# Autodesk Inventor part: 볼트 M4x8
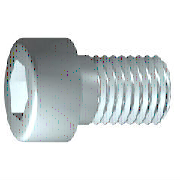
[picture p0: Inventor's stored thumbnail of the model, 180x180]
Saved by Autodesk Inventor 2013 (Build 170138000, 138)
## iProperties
Created: 2012-02
Part Number: 볼트 M4x8
Material: 스테인리스강
Description: 6각 소켓 머리 캡 나사
Document SubType Name: Modeling
Standard: ISO 4762
Designer: mduedu
Standard Revision: Fourth edition 2004-03-01
Standards Organization: ISO
Language: ko-KR
Size Designation: M4 x 8
Categories: <MemberInstance><Categories><Category DisplayName="조임쇠" InternalName="e4da775c-781d-43d5-af7c-5136215cf5a6" Mnemonic="FSTN"><Category DisplayName="볼트" InternalN
Density: 8.08 g/cm^3
Mass: 1.89105 g
Surface Area: 2.80587 cm^2
Volume: 0.234041 cm^3
IsCustomPart: 0
Author: mduedu
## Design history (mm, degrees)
sketch "스케치1"
  geometry: L1 (-1, 0)-(8, 0); L2 (8, 0)-(8, 2); L3 (8, 2)-(1.75, 2); L4 (1.75, 2)-(1.32, 2); L5 (1.32, 2)-(0, 2); L6 (0, 2)-(0, 3.5); L7 (0, 3.5)-(-4, 3.5); L8 (-4, 3.5)-(-4, 1.732); L9 (-4, 1.732)-(-2, 1.732); L10 (-2, 1.732)-(-1, 0); L11 (-6.4, 0)-(10.4, 0) reference; L12 (0, -0.7)-(0, 4.2) reference; L13 (1.75, 2)-(0, 2)
  constraints: 22 end point, 6 parallel, 2 collinear, 2 perpendicular, 1 horizontal, 1 point on line
  dimensions: "d1" = 6.25 distance from line of L3.end L2 (= GEL); "d2" = 0.42952 distance of L4.end L3.end (computed from GAL); "d3" = 4 distance between parallel lines of L8 L6 (= KOH); "d4" = 2 distance of L8.end L9.end (= INTI); "d5" = 60 deg angle of L10 L1; "d6" = 4 diameter of L3 L1 (= GD); "d7" = 4 diameter of L5 L1 (= BDM); "d8" = 3.4641 diameter of L9 L1 (= 1.1547 x SW); "d9" = 7 diameter of L7 L1 (= KOD); "d26" = 8 distance between parallel lines of L12 L2 (= NLG)
revolve "본체" sketch "스케치1" stored, may be unused: angle "d10" = 90 deg
sketch "스케치2"
  geometry: L1 (0, -4.9)-(0, 4.9) reference; L2 (-4.9, 0)-(4.9, 0) reference; L3 (1.732, 0)-(0.866, -1.5); L4 (0.866, -1.5)-(-0.866, -1.5); L5 (-0.866, -1.5)-(-1.732, 0); L6 (-1.732, 0)-(-0.866, 1.5); L7 (-0.866, 1.5)-(0.866, 1.5); L8 (0.866, 1.5)-(1.732, 0); 2 further points
  constraints: 12 end point, 1 coincident, 1 horizontal alignment, 1 point on line, 12 other
extrude "슬롯" join sketch "스케치2" stored distance "d11" = 10; taper "d12" = 0 deg
workplane "Work Plane1"
fillet "Fillet2" dims "d30" = 0.1 (= R)
body "Solid1"
fillet "모깎기1" dims "d17" = 0.4 (= RR)
feature "스레드" dims "d13" = 6.25 (= GEL), "d14" = 0
chamfer "모따기1" distance "d15" = 0.42941 (= -0.5 x SPD + 0.5 x GD); stored, may be unused: second distance "d16" = 0.42941 (= GUL), angle "d27" = 45 deg
other parameters: "GD" = 4 [user parameter; used in 2 equation terms], "NLG" = 8 [user parameter; used in 1 equation term], "GEL" = 6.25 [user parameter; used in 2 equation terms], "KOD" = 7 [user parameter; used in 1 equation term], "KOH" = 4 [user parameter; used in 1 equation term], "INTI" = 2 [user parameter; used in 1 equation term], "GAL" = 0.42941 (= 0.61345 x PTC) [user parameter; used in 1 equation term], "GUL" = 0.42941 (= 0.61345 x PTC) [user parameter; used in 1 equation term], "BDM" = 4 (= NND) [user parameter; used in 1 equation term], "SW" = 3 [user parameter; used in 2 equation terms], "RR" = 0.4 [user parameter; used in 1 equation term], "SPD" = 3.14117 (= NND - 1.2269 x PTC) [user parameter; used in 1 equation term], "d19" = 0, "d28" = 0, "d29" = 0, "R" = 0.1 [user parameter; used in 1 equation term], "TOA" = 30 deg [user parameter], "GD1" = 3.14117 (= THREADDIA - 1.2269 x PTC) [user parameter], "THREADDIA" = 4 [user parameter; used in 1 equation term], "FAWI" = 45 deg [user parameter], "TPU" = 14.28571 (computed from PTC) [user parameter], "PTC" = 0.7 [user parameter; used in 5 equation terms], "NND" = 4 [user parameter; used in 2 equation terms], "E0" = 3.465 (= 1.155 x SW) [user parameter]
